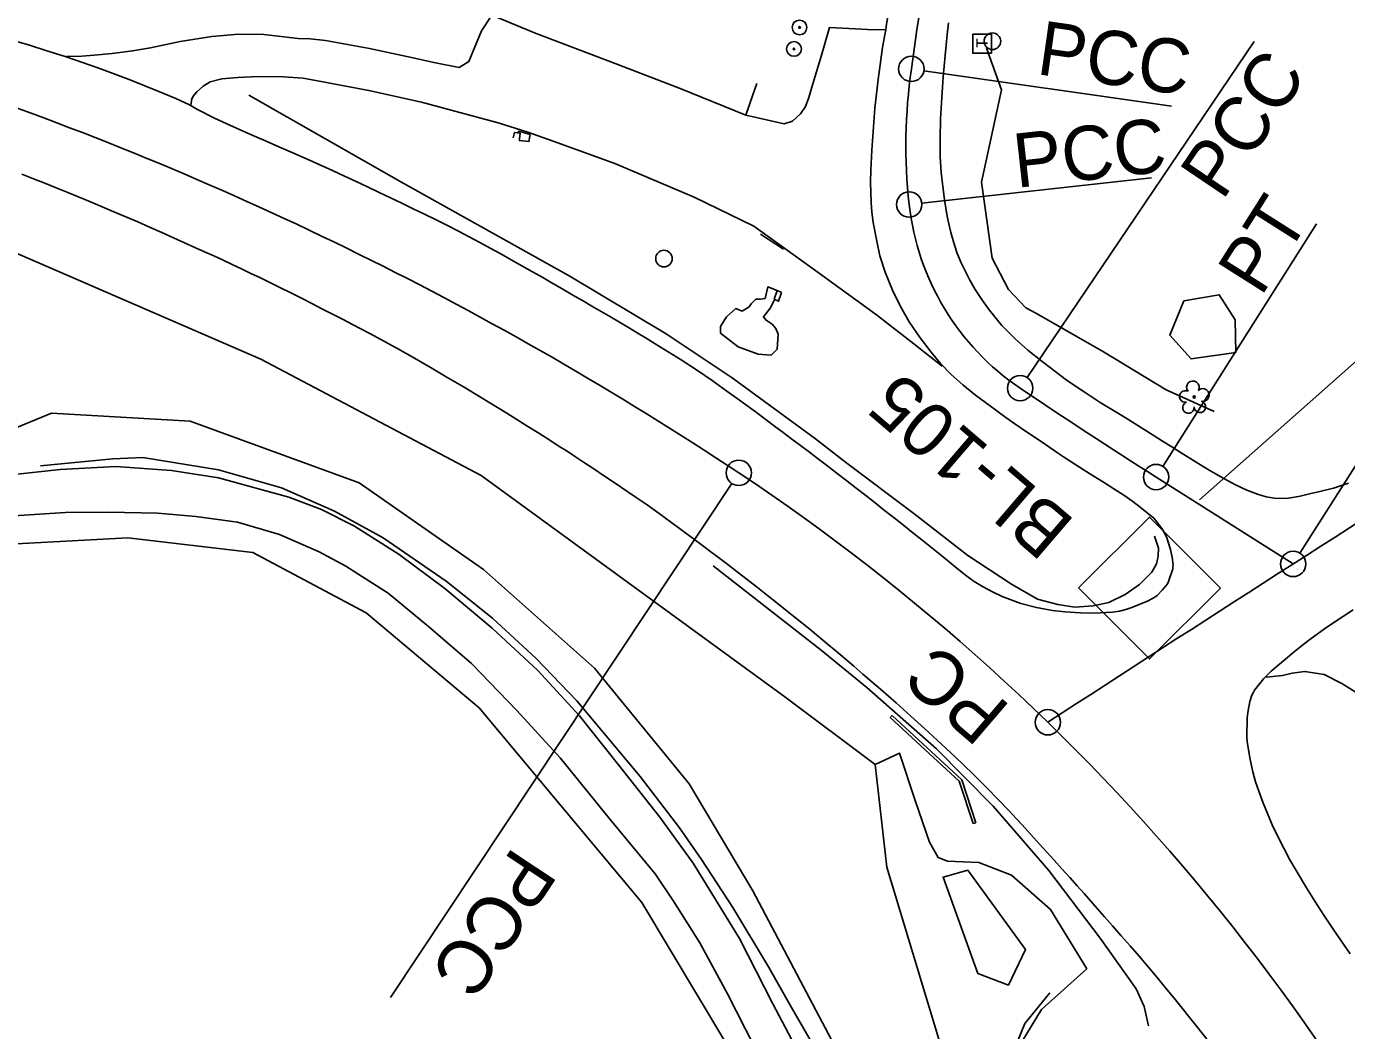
# Model space of a CAD drawing. Extents: x 478596 to 483012, y 490885 to 495165.
# Drawn here: x 480534.5 to 480925.2, y 493003.6 to 493300.7 of the extents above; entities that cross this region are included whole.
import ezdxf

# ---------------------------------------------------------------- set-up
doc = ezdxf.new("R2010")
doc.units = 0
for name, color, linetype in [('CTL Secondary Horizontal and Vertical CELL', 7, 'Continuous'), ('CTL Secondary Horizontal and Vertical Text', 7, 'Continuous'), ('Exist Guardrail', 7, 'Continuous'), ('Exist Horizontal Alignment', 7, 'Continuous'), ('Exist Horizontal Alignment Direction Label', 7, 'Continuous'), ('Exist Other Culture Area Outline', 7, 'Continuous'), ('Exist Other Culture Fence Line', 7, 'Continuous'), ('Exist Roads Change in Surface', 7, 'Continuous'), ('Exist Roads EOP', 7, 'Continuous'), ('Exist Roads EOP Other', 7, 'Continuous'), ('Exist Roads Soil', 7, 'Continuous'), ('Exist Structure Major Bridge WW', 7, 'Continuous'), ('Exist Structure Minor Head and End Wall', 7, 'Continuous'), ('Exist Utilities Other Located Object CELL', 7, 'Continuous'), ('Exist Utilities Other Pole CELL', 7, 'Continuous'), ('Exist Utilities Telephone Pedestal CELL', 7, 'Continuous'), ('Exist Vegetation Hedge Row', 7, 'Continuous'), ('Exist Vegetation Tree CELL', 7, 'Continuous'), ('Exist Vegetation Woods Line', 7, 'Continuous')]:
    doc.layers.add(name, color=color, linetype=linetype)

msp = doc.modelspace()

# ---------------------------------------------------------------- linework, layer by layer
at = {"layer": 'CTL Secondary Horizontal and Vertical CELL'}
msp.add_line((480866.76, 493134.49), (480866.76, 493134.49), dxfattribs=at)
msp.add_lwpolyline([(480845.9, 493134.56), (480866.86, 493155.53), (480887.86, 493134.53), (480866.9, 493113.56)], close=True, dxfattribs=at)
at = {"layer": 'Exist Guardrail'}
msp.add_line((480769.66, 493116.1), (480737.72, 493141.14), dxfattribs=at)
for points in [[(480600.29, 493280.43), (480645.29, 493254.71), (480695.14, 493226.95), (480723.78, 493209.8), (480743.37, 493196.71), (480768.06, 493178.7), (480776.92, 493171.74), (480797.09, 493156.62)], [(480538.63, 493170.65), (480560.01, 493172.79), (480568.89, 493173.11), (480591.35, 493169.53), (480609.95, 493164.16), (480625.63, 493157.29), (480640.07, 493149.38), (480658.73, 493136.54), (480672.42, 493125.6), (480685.38, 493113.66), (480697.37, 493101.14), (480716.09, 493078.74), (480727.74, 493063.53), (480734.29, 493054.23)], [(480797.09, 493156.62), (480813.1, 493144.15), (480826.07, 493135.67), (480833.69, 493131.21), (480839.69, 493129.63), (480844.75, 493128.91), (480850.23, 493129.28), (480854.82, 493130.29), (480859.7, 493132.61), (480863.95, 493135.53), (480867.57, 493139.21), (480868.91, 493141.68), (480869.48, 493143.95), (480869.56, 493146.35), (480868.31, 493149.85)], [(480866.57, 493004.94), (480865.28, 493010.7), (480862.91, 493015.92), (480852.24, 493030.9), (480837.12, 493050.92), (480820.62, 493070), (480803.82, 493086.93), (480783.25, 493105.1), (480769.66, 493116.1)], [(480734.29, 493054.23), (480743.58, 493039.99), (480754.13, 493022.46), (480760.96, 493010.37), (480772.27, 492990.77)]]:
    msp.add_lwpolyline(points, dxfattribs=at)
at = {"layer": 'Exist Horizontal Alignment'}
for p, q in [((480830.69, 493196.79), (480897.83, 493296.29)), ((480800.1, 493287.63), (480873.38, 493277.17)), ((480799.47, 493248.44), (480867.47, 493255.95)), ((480911.4, 493144.83), (480975.91, 493246.65)), ((480870.82, 493170.54), (480916.32, 493242.35)), ((480743.23, 493165.5), (480642.19, 493013.34)), ((480868.82, 493167.37), (480909.4, 493141.66))]:
    msp.add_line(p, q, dxfattribs=at)
for centre in [(480796.38, 493288.16), (480795.75, 493248.03), (480828.59, 493193.68), (480745.3, 493168.62), (480868.82, 493167.37), (480909.4, 493141.66), (480836.79, 493094.8)]:
    msp.add_circle(centre, 3.75, dxfattribs=at)
for centre, radius, start, end in [((630504.98, 471924.64), 151225.21, 171.8431343, 171.8786811), ((480954.66, 493265.57), 159.88, 171.8787, 186.2992), ((480184.05, 492323.44), 1014.56, 56.41358, 71.08844), ((488084.67, 481943.17), 13300.03, 121.626761, 123.021402), ((480870.86, 493256.32), 75.57, 186.2992, 235.989), ((481759.98, 494573.95), 1665.12, 235.98896, 237.64291), ((480394.24, 492639.96), 634.61, 22.51531, 56.41358)]:
    msp.add_arc(centre, radius, start, end, dxfattribs=at)
at = {"layer": 'Exist Horizontal Alignment Direction Label'}
msp.add_lwpolyline([(480881.69, 493160.66), (480929.89, 493203.3), (480993.05, 493148.93)], dxfattribs=at)
at = {"layer": 'Exist Other Culture Area Outline'}
for points in [[(480680.38, 493267.44), (480680.37, 493266.94), (480683.22, 493266.65), (480683.56, 493268.74), (480680.13, 493269.73), (480679.97, 493269.19)], [(480753.15, 493220.17), (480751.71, 493219.99), (480750.31, 493219.99), (480748.97, 493218.68), (480748.39, 493217.78), (480746.27, 493216.42)], [(480756.66, 493222.58), (480757.94, 493221.95), (480757.05, 493219.42), (480755.79, 493220.04)], [(480746.27, 493216.42), (480744.48, 493217.29), (480741.63, 493214.74), (480739.92, 493211.93), (480739.93, 493209.96), (480745.08, 493205.89), (480751.04, 493203.76), (480754.86, 493203.42), (480756.7, 493205.22), (480756.95, 493209.68), (480756.28, 493211.35), (480755.16, 493212.65), (480753.37, 493213.78), (480752.61, 493214.83), (480754.7, 493217.46), (480755.8, 493219.68)]]:
    msp.add_lwpolyline(points, dxfattribs=at)
at = {"layer": 'Exist Other Culture Fence Line'}
for points in [[(480830.28, 493217.46), (480825.11, 493222.85), (480820.31, 493232.11), (480817.16, 493254.65), (480823.04, 493281.94), (480818.59, 493294.29)], [(480885.97, 493186.82), (480871.78, 493193.15), (480853.22, 493204.39), (480833.4, 493215.74), (480830.28, 493217.46)], [(480837.39, 493014.74), (480829.96, 493005.68), (480827.79, 493000.38), (480827.65, 492995.09), (480828.86, 492986.87), (480834.06, 492970.34), (480841.42, 492954.84), (480853.25, 492935.25)]]:
    msp.add_lwpolyline(points, dxfattribs=at)
at = {"layer": 'Exist Roads Change in Surface'}
msp.add_lwpolyline([(480672.19, 493304.04), (480685.32, 493298.61), (480708.69, 493289.73), (480727.92, 493282.31), (480747.36, 493274.45)], dxfattribs=at)
at = {"layer": 'Exist Roads EOP'}
for points in [[(480789.7, 493305.5), (480788.95, 493300.7), (480788.79, 493299.7), (480788.5, 493298.26), (480787.87, 493294.5), (480787.31, 493290.84), (480786.52, 493284.99), (480786.04, 493280.81), (480785.61, 493276.56), (480785.25, 493272.4), (480784.94, 493268.26), (480784.64, 493264.1), (480784.36, 493258.16), (480784.34, 493254.59), (480784.45, 493248.67), (480784.7, 493245.76), (480785.13, 493242.68), (480786.13, 493237.13), (480787.06, 493232.88), (480788.59, 493227.96), (480790.77, 493222.66), (480793.14, 493217.88), (480795.7, 493213.27), (480798.96, 493208.54), (480802.24, 493204.3), (480805.01, 493200.94), (480808.15, 493197.76), (480811.64, 493194.63), (480815.37, 493191.57), (480819.77, 493188.31), (480824.32, 493185.04), (480827.03, 493183.15), (480830.17, 493181), (480833.29, 493178.86), (480836.36, 493176.76), (480839.68, 493174.54), (480841.46, 493173.39), (480844.8, 493171.23), (480847.58, 493169.45), (480850.24, 493167.76), (480853.24, 493165.87), (480856.32, 493163.9), (480859.26, 493161.98), (480861.92, 493160.15), (480864.15, 493158.48), (480868.12, 493155.17), (480868.97, 493154.21), (480870.47, 493152.19), (480871.54, 493150.43), (480871.98, 493149.39), (480873.04, 493145.89), (480873.68, 493143.08), (480873.82, 493141.87), (480873.84, 493141.29), (480873.81, 493140.75), (480873.74, 493140.25), (480872.51, 493136.51), (480872.15, 493135.8), (480871.73, 493135.14), (480870.74, 493133.95), (480869.09, 493132.37), (480868.41, 493131.86), (480866.45, 493130.77), (480861.63, 493128.76), (480859.88, 493128.18), (480858.01, 493127.71), (480855.9, 493127.34), (480850.38, 493127.07), (480846.45, 493127.21), (480841.8, 493127.53), (480838.19, 493127.89), (480833.4, 493128.75), (480828.83, 493129.97), (480823.3, 493132.01), (480820.55, 493133.27), (480817.45, 493134.99), (480814.97, 493136.47), (480812.76, 493138.06), (480809.92, 493140.32), (480805.89, 493143.62), (480801.92, 493146.85), (480799.53, 493148.76), (480796.86, 493150.88), (480794.06, 493153.1), (480791.27, 493155.31), (480788.47, 493157.51), (480785.69, 493159.71), (480782.89, 493161.91), (480780.09, 493164.09), (480777.28, 493166.27), (480774.46, 493168.44), (480771.67, 493170.59), (480768.92, 493172.67), (480766.23, 493174.7), (480763.6, 493176.67), (480761.01, 493178.61), (480758.44, 493180.53), (480755.9, 493182.43), (480753.39, 493184.3), (480750.93, 493186.14), (480746.24, 493189.61), (480741.81, 493192.83), (480737.45, 493195.92), (480733.05, 493198.94), (480728.28, 493202.03), (480725.74, 493203.63), (480723.13, 493205.23), (480720.52, 493206.84), (480717.9, 493208.44), (480715.28, 493210.04), (480712.64, 493211.63), (480709.98, 493213.22), (480707.3, 493214.8), (480704.6, 493216.37), (480701.86, 493217.96), (480699.06, 493219.58), (480696.19, 493221.24), (480693.26, 493222.93), (480690.28, 493224.65), (480687.27, 493226.38), (480684.21, 493228.13), (480681.11, 493229.89), (480677.99, 493231.65), (480674.88, 493233.39), (480671.77, 493235.1), (480668.67, 493236.78), (480665.54, 493238.45), (480662.33, 493240.13), (480659.05, 493241.8), (480655.7, 493243.47), (480652.31, 493245.14), (480648.93, 493246.79), (480645.56, 493248.42), (480642.2, 493250.03), (480638.83, 493251.63), (480635.43, 493253.24), (480632.02, 493254.85), (480628.58, 493256.46), (480625.03, 493258.11), (480621.3, 493259.8), (480617.38, 493261.55), (480613.28, 493263.35), (480609.22, 493265.12), (480605.45, 493266.76), (480601.98, 493268.28), (480598.78, 493269.68), (480593.57, 493271.99), (480590.11, 493273.58), (480585.15, 493276.13), (480582.76, 493277.54), (480578.72, 493279.35), (480573.7, 493281.47), (480569.54, 493283.17), (480564.87, 493285.04), (480560.18, 493286.83), (480555.61, 493288.49), (480551.41, 493289.98), (480545.91, 493291.84), (480540.22, 493293.61), (480535.38, 493295.14), (480530.23, 493296.67)], [(480807.39, 493301.77), (480807, 493298.35), (480806.66, 493295.14), (480806.36, 493292.08), (480806.09, 493288.96), (480805.82, 493285.77), (480805.6, 493282.66), (480805.41, 493279.65), (480805.22, 493276.56), (480805.06, 493273.39), (480804.88, 493267.45), (480804.96, 493262.11), (480805.22, 493257.52), (480805.67, 493253.31), (480806.15, 493249.54), (480806.8, 493245.64), (480807.19, 493243.61), (480808.07, 493239.77), (480808.97, 493236.66), (480809.89, 493233.84), (480811.03, 493230.92), (480813.66, 493225.66), (480815.27, 493222.92), (480817.46, 493219.59), (480819.44, 493216.87), (480823.17, 493212.24), (480827.15, 493208.25), (480830.9, 493204.97), (480835.08, 493201.59), (480837.55, 493199.66), (480840.12, 493197.71), (480842.63, 493195.89), (480847.49, 493192.59), (480852.29, 493189.48), (480857.17, 493186.46), (480859.92, 493184.78), (480862.64, 493183.12), (480865.29, 493181.48), (480867.98, 493179.79), (480870.71, 493178.03), (480873.49, 493176.27), (480876.25, 493174.53), (480880.67, 493171.8), (480884.57, 493169.46), (480888.83, 493166.94), (480892.3, 493165.08), (480895.63, 493163.5), (480898.81, 493162.26), (480901.42, 493161.51), (480903.22, 493161.18), (480904.54, 493161.05), (480908.01, 493161.17), (480911.51, 493161.76), (480914.25, 493162.38), (480917.68, 493163.15), (480921.34, 493164.1), (480925.78, 493165.57)], [(480884.22, 493000.53), (480880.91, 493004.73), (480878.81, 493007.37), (480876.51, 493010.23), (480874.13, 493013.17), (480871.65, 493016.2), (480869.09, 493019.31), (480866.47, 493022.45), (480863.84, 493025.55), (480861.19, 493028.61), (480858.52, 493031.64), (480855.94, 493034.54), (480853.57, 493037.22), (480851.39, 493039.68), (480847.49, 493044.1), (480845.43, 493046.41), (480843.26, 493048.85), (480840.96, 493051.42), (480838.67, 493053.97), (480836.5, 493056.36), (480832.56, 493060.7), (480829.14, 493064.44), (480827.62, 493066.09), (480824.92, 493068.98), (480822.41, 493071.62), (480818.53, 493075.59), (480815.17, 493078.94), (480811.5, 493082.53), (480807.87, 493085.97), (480804.17, 493089.4), (480800.29, 493092.96), (480796.2, 493096.66), (480791.89, 493100.52), (480789.61, 493102.53), (480787.22, 493104.63), (480784.7, 493106.81), (480782.07, 493109.08), (480779.39, 493111.38), (480776.74, 493113.63), (480774.1, 493115.85), (480771.49, 493118.04), (480768.93, 493120.16), (480766.42, 493122.22), (480763.99, 493124.2), (480761.61, 493126.11), (480759.18, 493128.05), (480756.57, 493130.12), (480753.78, 493132.33), (480750.8, 493134.68), (480747.79, 493137.05), (480744.86, 493139.32), (480742.03, 493141.49), (480739.28, 493143.57), (480736.65, 493145.53), (480734.16, 493147.39), (480729.6, 493150.79), (480725.49, 493153.82), (480721.73, 493156.56), (480718.17, 493159.11), (480714.66, 493161.54), (480710.58, 493164.31), (480708.09, 493165.98), (480705.29, 493167.85), (480702.4, 493169.77), (480699.63, 493171.6), (480696.99, 493173.34), (480694.47, 493174.99), (480691.9, 493176.65), (480689.11, 493178.44), (480686.1, 493180.34), (480682.87, 493182.37), (480679.65, 493184.38), (480676.65, 493186.25), (480673.87, 493187.97), (480668.87, 493191.02), (480664.02, 493193.93), (480659.2, 493196.77), (480654.27, 493199.66), (480649.29, 493202.55), (480644.76, 493205.11), (480640.63, 493207.37), (480636.09, 493209.82), (480631, 493212.52), (480628.21, 493213.97), (480625.27, 493215.5), (480622.15, 493217.09), (480618.98, 493218.7), (480615.84, 493220.29), (480612.74, 493221.85), (480609.67, 493223.37), (480606.67, 493224.86), (480603.74, 493226.29), (480600.9, 493227.65), (480598.13, 493228.97), (480595.4, 493230.25), (480592.66, 493231.52), (480589.92, 493232.79), (480587.18, 493234.05), (480584.33, 493235.35), (480581.27, 493236.73), (480578, 493238.2), (480574.52, 493239.75), (480570.95, 493241.32), (480567.4, 493242.87), (480563.87, 493244.39), (480560.37, 493245.89), (480556.9, 493247.35), (480553.46, 493248.79), (480550.06, 493250.19), (480546.69, 493251.57), (480543.32, 493252.93), (480539.93, 493254.3), (480536.52, 493255.67), (480533.07, 493257.05)], [(480927.12, 493128.09), (480924.26, 493126.23), (480919.4, 493122.92), (480914.75, 493119.57), (480912.24, 493117.68), (480909.68, 493115.66), (480907.17, 493113.59), (480902.87, 493109.88), (480900.7, 493107.77), (480897.92, 493104.27), (480897.51, 493103.55), (480897.18, 493102.82), (480896.59, 493100.91), (480896.04, 493098.29), (480895.77, 493096.11), (480895.68, 493090.47), (480895.76, 493089.02), (480896.62, 493083.76), (480897.41, 493080.18), (480898.24, 493077.22), (480899.2, 493074.38), (480900.39, 493071.16), (480901.75, 493067.76), (480903.21, 493064.42), (480904.82, 493061.04), (480906.6, 493057.54), (480908.44, 493054.11), (480910.23, 493050.94), (480913.32, 493045.81), (480915.82, 493041.83), (480918.45, 493037.76), (480921.22, 493033.59), (480924.44, 493028.86), (480926.24, 493026.25)]]:
    msp.add_lwpolyline(points, dxfattribs=at)
at = {"layer": 'Exist Roads EOP Other'}
for points in [[(480675.35, 493312.36), (480672.19, 493304.04), (480669.18, 493299.4), (480665.43, 493290.31), (480662.59, 493288.55)], [(480614.95, 493297.12), (480604.76, 493298.35), (480597.34, 493298.43), (480589.35, 493297.73), (480579.95, 493296.23), (480571.18, 493294.37), (480565.91, 493293.47), (480559.86, 493292.68), (480554.54, 493292.18), (480550.91, 493291.96), (480546.33, 493291.81)], [(480788.68, 493299.85), (480785.1, 493299.68), (480781.77, 493299.9), (480772.2, 493300.42), (480769.56, 493291.58), (480767.25, 493283.78), (480766, 493279.66), (480765.06, 493277.04), (480763.55, 493274.82), (480761.24, 493272.67), (480758.72, 493271.89), (480747.36, 493274.45)], [(480614.95, 493297.12), (480618.41, 493297.07), (480622.97, 493296.56), (480635.97, 493294.18), (480647.03, 493291.84), (480655.52, 493289.98), (480662.59, 493288.55)], [(480583.2, 493277.6), (480583.33, 493278.99), (480583.8, 493280.06), (480584.87, 493281.39), (480586.76, 493283.06), (480588.83, 493284.34), (480592.29, 493285.2), (480597.02, 493285.58), (480603.09, 493285.94), (480610.57, 493285.78), (480616.4, 493285.39)], [(480749.78, 493241.62), (480732.13, 493250.17), (480708.63, 493260.2), (480690.41, 493266.82), (480682.9, 493269.47), (480674.06, 493272.21), (480651.43, 493278.33), (480635.79, 493281.74), (480622.19, 493284.36), (480616.4, 493285.39)], [(480747.36, 493274.45), (480749.48, 493280.47), (480750.69, 493283.79)], [(480805.46, 493200.19), (480797.09, 493206.82), (480786.1, 493215.34), (480768.8, 493227.92), (480749.78, 493241.62)], [(480758.55, 493234.8), (480751.7, 493239.21)]]:
    msp.add_lwpolyline(points, dxfattribs=at)
at = {"layer": 'Exist Roads Soil'}
for points in [[(480731.82, 493053.11), (480721.95, 493066.73), (480709.7, 493082.22), (480698.12, 493096.69), (480685.79, 493110.1), (480672.35, 493122.67), (480658.28, 493134.4), (480644.84, 493144.43), (480631.58, 493152.79), (480621.79, 493157.74), (480612.16, 493161.4), (480591.29, 493167.1), (480577.43, 493169.3), (480560.94, 493170.49), (480544.44, 493169.56), (480529.92, 493168.05), (480515.54, 493164.56)], [(480720.54, 493049.96), (480707.27, 493066.03), (480692.47, 493084.33), (480679.65, 493098.24), (480666.2, 493112.15), (480653.49, 493123.18), (480641.49, 493133), (480629.04, 493141.05), (480621.09, 493145.28), (480609.33, 493150.38), (480596.94, 493154), (480584.65, 493155.73), (480573.41, 493156.71), (480558.54, 493157.03), (480546, 493156.86), (480532.21, 493155.99), (480517.3, 493152.44)], [(480998, 492994.13), (480990.09, 493004.5), (480983.8, 493013.53), (480978.48, 493022.43), (480971.22, 493033.88), (480962.36, 493049.94), (480955.25, 493064.31), (480948.78, 493076.48), (480942.89, 493088.29), (480939.18, 493094.32), (480936.19, 493097.32), (480932.09, 493100.75), (480927.73, 493103.82), (480923.76, 493106.25), (480918.57, 493108.9), (480912.88, 493109.87), (480909.09, 493109.29), (480906.23, 493108.61), (480901.36, 493108.13)], [(480731.82, 493053.11), (480745.57, 493030.81), (480755.43, 493011.44), (480765.56, 492992.25)], [(480836.23, 492901.3), (480825.85, 492904.14), (480816.04, 492908.4), (480805.75, 492913.33), (480798.74, 492917.81), (480793.73, 492922.17), (480788.99, 492927.46), (480783.78, 492935.47), (480775.9, 492948.54), (480762.17, 492975.19), (480752.7, 492993.36), (480741.93, 493014.47), (480733.78, 493029.56), (480725.94, 493041.88), (480720.54, 493049.96)]]:
    msp.add_lwpolyline(points, dxfattribs=at)
at = {"layer": 'Exist Structure Major Bridge WW'}
for p, q in [((480810.57, 493077.34), (480814.68, 493064.8)), ((480811.29, 493077.8), (480815.47, 493065.06))]:
    msp.add_line(p, q, dxfattribs=at)
at = {"layer": 'Exist Structure Minor Head and End Wall'}
for p, q in [((480790.12, 493096.21), (480790.69, 493096.82)), ((480790.12, 493096.21), (480810.57, 493077.34)), ((480790.69, 493096.82), (480811.29, 493077.8)), ((480814.68, 493064.8), (480815.47, 493065.06))]:
    msp.add_line(p, q, dxfattribs=at)
for points in [[(480678.57, 493267.77), (480678.96, 493269.32), (480680.56, 493269.12), (480680.38, 493267.44)], [(480753.15, 493220.17), (480753.86, 493223.63), (480756.66, 493222.58), (480755.79, 493220.04)]]:
    msp.add_lwpolyline(points, dxfattribs=at)
at = {"layer": 'Exist Utilities Other Located Object CELL'}
for centre, radius in [((480763.29, 493300.42), 2.18), ((480763.29, 493300.42), 0.24), ((480761.66, 493294.06), 2.18), ((480761.66, 493294.06), 0.24)]:
    msp.add_circle(centre, radius, dxfattribs=at)
at = {"layer": 'Exist Utilities Other Pole CELL'}
for centre in [(480820.36, 493296.34), (480723.17, 493232.01)]:
    msp.add_circle(centre, 2.46, dxfattribs=at)
at = {"layer": 'Exist Utilities Telephone Pedestal CELL'}
msp.add_line((480817.31, 493295.52), (480817.31, 493295.52), dxfattribs=at)
msp.add_lwpolyline([(480820.13, 493292.8), (480820.13, 493298.39), (480814.54, 493298.39), (480814.54, 493292.8), (480820.13, 493292.8)], dxfattribs=at)
at = {"layer": 'Exist Vegetation Hedge Row'}
for points in [[(480892.45, 493204.24), (480879.16, 493202.31), (480872.86, 493209.36), (480877.06, 493219.5), (480887.51, 493221.33), (480892.25, 493213.87), (480892.45, 493204.24)], [(480785.66, 493082.33), (480792.85, 493085.7), (480797.51, 493071.62), (480801.79, 493059.31), (480804.35, 493054.77), (480807.13, 493053.68), (480816.31, 493053.32), (480826.06, 493049.57), (480837.61, 493039.41), (480848.28, 493021.88), (480834.86, 493009.84), (480828.82, 492999.78), (480832.03, 492983.49), (480839.99, 492961.09), (480856.08, 492935.53), (480856.93, 492931.37), (480847.59, 492925.15), (480842.61, 492921.18), (480839.34, 492917.38)]]:
    msp.add_lwpolyline(points, dxfattribs=at)
at = {"layer": 'Exist Vegetation Tree CELL'}
msp.add_line((480880.09, 493191.05), (480880.09, 493191.05), dxfattribs=at)
msp.add_circle((480880.09, 493191.05), 0.326, dxfattribs=at)
for centre, radius, start, end in [((480877.49, 493191.21), 1.73, 62.6636, 279.3457), ((480879.71, 493193.93), 1.86, 330.1651, 219.7134), ((480882.64, 493191.64), 1.9, 257.1011, 134.1999), ((480878.39, 493187.93), 1.69, 111.5671, 6.231), ((480881.77, 493188.15), 1.7, 181.2822, 74.56)]:
    msp.add_arc(centre, radius, start, end, dxfattribs=at)
at = {"layer": 'Exist Vegetation Woods Line'}
for points in [[(480440.45, 493268.72), (480506.54, 493244.38), (480603.86, 493202.26), (480669.06, 493167.83), (480758.97, 493102.29)], [(480730.58, 493076.57), (480702.59, 493110.84), (480669.75, 493139.99), (480632.94, 493165.71), (480582.98, 493183.96), (480541.91, 493186.28), (480493.77, 493166.45), (480469.01, 493152.06), (480434.17, 493107.43), (480421.28, 493073.75), (480418.33, 493066.31)], [(480441.22, 493058.39), (480444.06, 493068.65), (480456.79, 493106.6), (480489.18, 493138.92), (480516.69, 493146.78), (480564.5, 493149.4), (480601.45, 493145.09), (480635.06, 493127.16), (480668.43, 493099.05), (480716.65, 493041.49)], [(480758.97, 493102.29), (480785.66, 493082.33)], [(480785.66, 493082.33), (480785.66, 493082.33), (480789.12, 493051.96), (480807.06, 492992.55), (480821.45, 492947.33), (480842.94, 492926.16), (480839.34, 492917.38), (480812.74, 492935.09), (480799.61, 492943.95), (480779.83, 492978.74), (480772.8, 493000.8), (480749.44, 493044.91), (480730.58, 493076.57)], [(480813.09, 493051), (480830.21, 493027.58), (480825.12, 493017.03), (480816.09, 493020.5), (480805.78, 493048.99), (480813.09, 493051)], [(480716.65, 493041.49), (480741.51, 492999.94), (480773.32, 492931.13), (480788.68, 492912.69), (480813.95, 492897.48), (480831.05, 492888.02), (480813.24, 492854.4), (480789.12, 492826.33), (480765.86, 492816.22), (480761.77, 492806.65), (480759.63, 492805.16)]]:
    msp.add_lwpolyline(points, dxfattribs=at)

# ---------------------------------------------------------------- texts
at = {"layer": 'CTL Secondary Horizontal and Vertical Text'}
msp.add_text('BL-105', height=16, rotation=139.3796, dxfattribs=at).set_placement((480845.28, 493154.18))
at = {"layer": 'Exist Horizontal Alignment'}
for s, rotation, p in [('PCC', 351.8787, (480833.09, 493286.65)), ('PCC', 55.989, (480888.44, 493248.91)), ('PCC', 6.2992, (480827.49, 493252.93)), ('PT', 57.6429, (480899.88, 493220.49)), ('PC', 139.3794, (480826.2, 493099.29)), ('PCC', 236.4136, (480678.64, 493058.45))]:
    msp.add_text(s, height=16, rotation=rotation, dxfattribs=at).set_placement(p)
at = {"layer": 'Exist Utilities Telephone Pedestal CELL'}
msp.add_text('T', height=3.42, rotation=90, dxfattribs=at).set_placement((480819.02, 493294.39))

doc.saveas('drawing.dxf')
